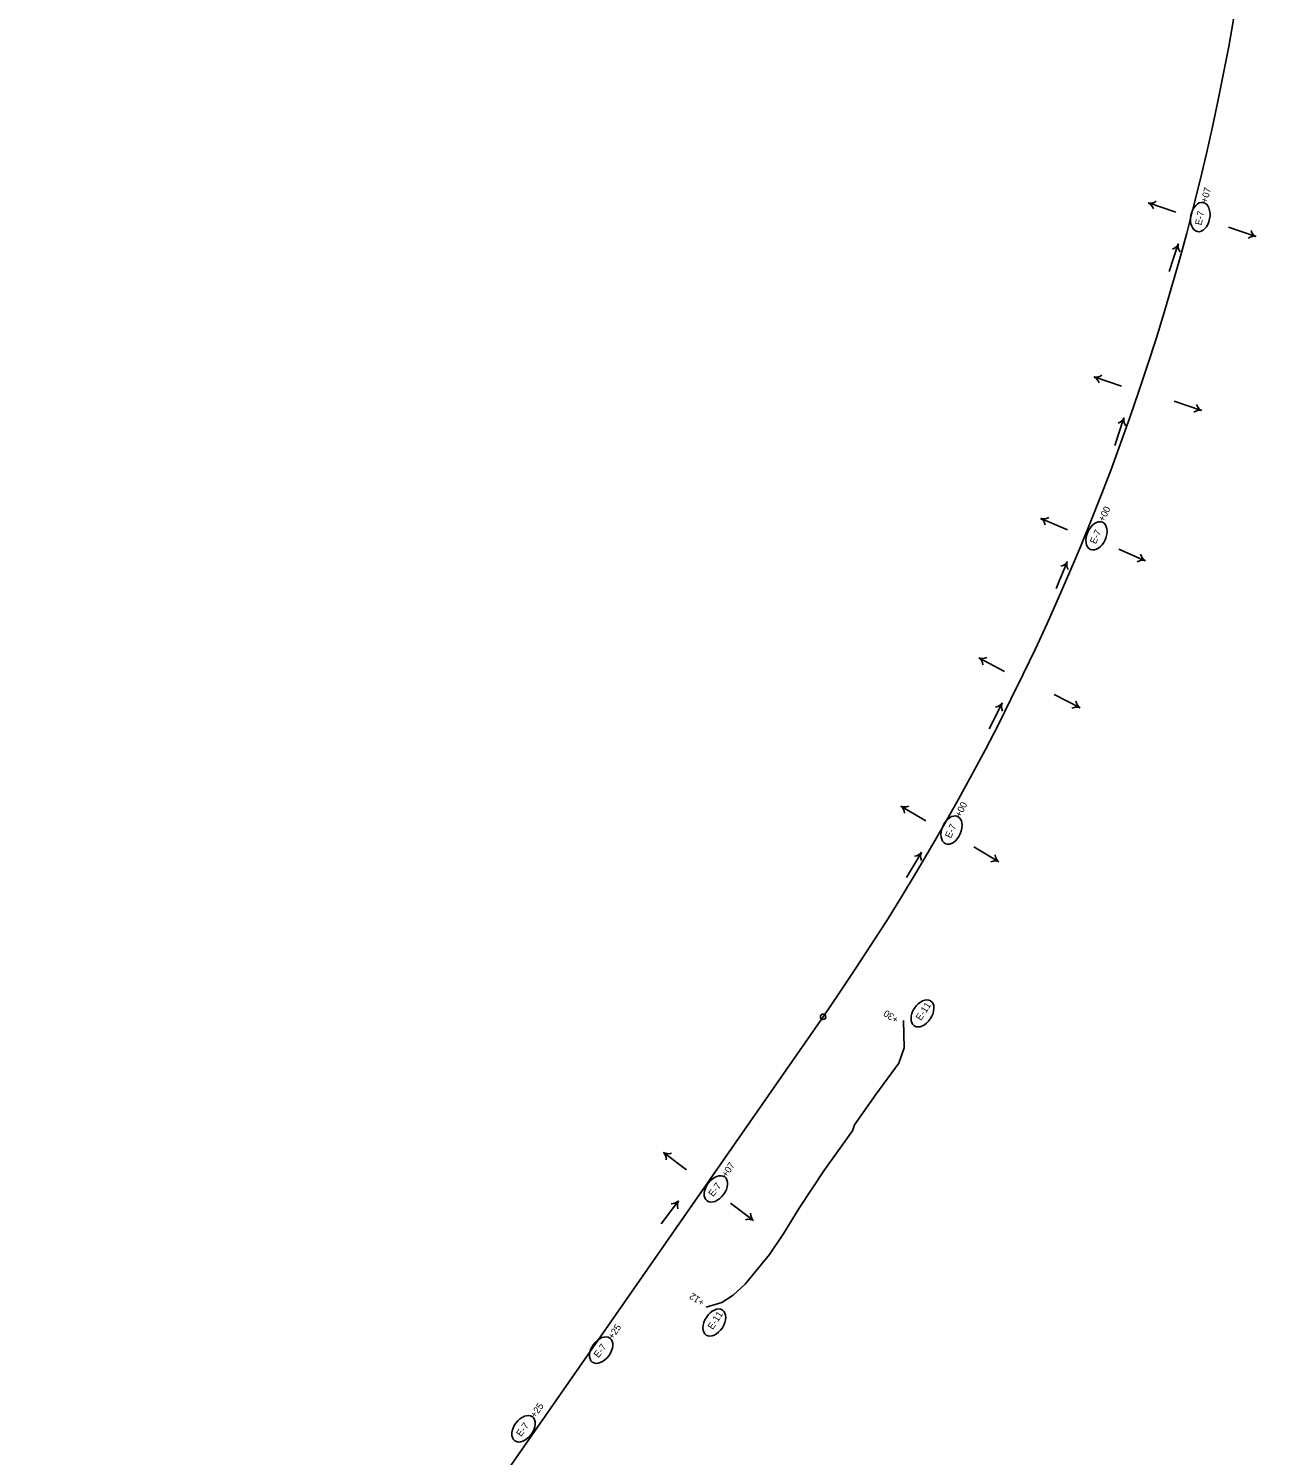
# Model space of a CAD drawing. Extents: x 669236 to 673912, y 735758 to 754788.
# Drawn here: x 672712 to 673851, y 748174 to 749484 of the extents above; entities that cross this region are included whole.
import ezdxf

# ---------------------------------------------------------------- set-up
doc = ezdxf.new("R2010")
doc.units = 0
for name, color, linetype in [('Default', 7, 'Continuous'), ('Prop_Horiz Alignment', 7, 'Continuous'), ('R_Erosion_2', 7, 'Continuous'), ('R_Flow Arrows', 7, 'Continuous')]:
    doc.layers.add(name, color=color, linetype=linetype)

msp = doc.modelspace()

# ---------------------------------------------------------------- linework, layer by layer
at = {"layer": 'Default'}
msp.add_line((671572, 745891.2), (673440.9, 748577.2), dxfattribs=at)
msp.add_arc((671559.6, 749886.2), 2291.8, 325.1701, 46.1906, dxfattribs=at)
at = {"layer": 'Prop_Horiz Alignment'}
msp.add_circle((673440.9, 748577.2), 2.5, dxfattribs=at)
at = {"layer": 'R_Erosion_2'}
msp.add_lwpolyline([(673333.6, 748310.7), (673348.1, 748314.8), (673358.3, 748321.7), (673369.3, 748331.7), (673391.6, 748358.9), (673404.8, 748378.7), (673418.8, 748401.5), (673441.5, 748435.8), (673467.8, 748472.5), (673469.6, 748478.1), (673489.4, 748506), (673510.4, 748534.7), (673515.2, 748548.7), (673514.6, 748573.8)], dxfattribs=at)
for centre, major_axis in [((673787.1, 749311.4), (2.6, 13.4)), ((673691.8, 749018.7), (5.5, 12.5)), ((673558.8, 748748.6), (5.5, 12.5)), ((673532.1, 748580.3), (7.5, 11.5)), ((673342.5, 748419.2), (8.1, 11)), ((673341.1, 748296.5), (7.5, 11.5)), ((673237.2, 748271.2), (8.1, 11)), ((673166, 748199), (8.1, 11))]:
    msp.add_ellipse(centre, major_axis=major_axis, ratio=0.638788, dxfattribs=at)
at = {"layer": 'R_Flow Arrows'}
for p, q in [((673739.5, 749324.3), (673764.7, 749315.8)), ((673838.2, 749293.5), (673813, 749302)), ((673766.9, 749286.7), (673758.6, 749261.5)), ((673689.6, 749164.6), (673714.8, 749156.1)), ((673788.3, 749133.7), (673763.1, 749142.2)), ((673717, 749127), (673708.7, 749101.7)), ((673640.7, 749034.7), (673665.1, 749024.2)), ((673736.6, 748995.9), (673712.2, 749006.4)), ((673665, 748994.9), (673654.7, 748970.5)), ((673583.9, 748906.6), (673607.5, 748894.3)), ((673676.7, 748860.9), (673653.1, 748873.2)), ((673605.2, 748865.2), (673593.2, 748841.5)), ((673512.3, 748770.6), (673535.1, 748757)), ((673602.2, 748719.5), (673579.4, 748733.1)), ((673531.1, 748728.1), (673517.6, 748705.2)), ((673294.4, 748452.7), (673315.5, 748436.6)), ((673308.3, 748408.3), (673292.4, 748387)), ((673377, 748390.1), (673355.8, 748406.2))]:
    msp.add_line(p, q, dxfattribs=at)
for centre, major_axis, start_param, end_param in [((673732.6, 749305.4), (6.4, 19.1), 5.662936, 6.259934), ((673745.7, 749343.5), (-6.4, -19.1), 0.023252, 0.620249), ((673832, 749274.3), (6.4, 19.1), 0.023252, 0.620249), ((673845.1, 749312.4), (-6.4, -19.1), 5.662936, 6.259934), ((673747.9, 749293.4), (19.2, -6.3), 5.662936, 6.259934), ((673786.2, 749280.7), (-19.2, 6.3), 0.023252, 0.620249), ((673682.7, 749145.6), (6.4, 19.1), 5.662936, 6.259934), ((673695.8, 749183.8), (-6.4, -19.1), 0.023252, 0.620249), ((673795.2, 749152.7), (-6.4, -19.1), 5.662936, 6.259934), ((673698, 749133.7), (19.2, -6.3), 5.662936, 6.259934), ((673736.3, 749121), (-19.2, 6.3), 0.023252, 0.620249), ((673782.1, 749114.6), (6.4, 19.1), 0.023252, 0.620249), ((673632.3, 749016.3), (8, 18.5), 5.662936, 6.259934), ((673648.4, 749053.3), (-8, -18.5), 0.023252, 0.620249), ((673646.6, 749003.2), (18.6, -7.8), 5.662936, 6.259934), ((673683.6, 748987.4), (-18.6, 7.8), 0.023252, 0.620249), ((673728.8, 748977.3), (8, 18.5), 0.023252, 0.620249), ((673744.9, 749014.2), (-8, -18.5), 5.662936, 6.259934), ((673574.2, 748888.9), (9.3, 17.9), 5.662936, 6.259934), ((673593, 748924.6), (-9.3, -17.9), 0.023252, 0.620249), ((673587.5, 748874.7), (18, -9.1), 5.662936, 6.259934), ((673623.3, 748856.3), (-18, 9.1), 0.023252, 0.620249), ((673667.6, 748842.9), (9.3, 17.9), 0.023252, 0.620249), ((673686.4, 748878.6), (-9.3, -17.9), 5.662936, 6.259934), ((673501.6, 748753.6), (10.4, 17.3), 5.662936, 6.259934), ((673522.4, 748788.1), (-10.4, -17.3), 0.023252, 0.620249), ((673513.9, 748738.6), (17.4, -10.2), 5.662936, 6.259934), ((673548.6, 748718.1), (-17.4, 10.2), 0.023252, 0.620249), ((673592, 748702), (10.4, 17.3), 0.023252, 0.620249), ((673612.9, 748736.5), (-10.4, -17.3), 5.662936, 6.259934), ((673281.8, 748436.9), (12.2, 16), 5.662936, 6.259934), ((673306.4, 748468.9), (-12.2, -16), 0.023252, 0.620249), ((673292.4, 748420.7), (16.1, -12.1), 5.662936, 6.259934), ((673324.6, 748396.4), (-16.1, 12.1), 0.023252, 0.620249), ((673365, 748373.9), (12.2, 16), 0.023252, 0.620249), ((673389.5, 748405.9), (-12.2, -16), 5.662936, 6.259934)]:
    msp.add_ellipse(centre, major_axis=major_axis, ratio=0.5625, start_param=start_param, end_param=end_param, dxfattribs=at)

# ---------------------------------------------------------------- texts
at = {"layer": 'R_Erosion_2'}
for s, rotation, p in [('+07', 74.6242, (673793.3, 749323.9)), ('E-7', 78.8894, (673788.3, 749303.5)), ('+00', 63.4208, (673698.6, 749031.1)), ('E-7', 66.359, (673691.2, 749010.7)), ('+00', 63.4208, (673567.1, 748759.8)), ('E-7', 66.359, (673558.2, 748740.6)), ('E-11', 56.9613, (673530.7, 748573.2)), ('+30', 146.1843, (673510.8, 748576)), ('+07', 55.5768, (673352.3, 748429.2)), ('E-7', 53.5441, (673340.1, 748411.5)), ('+12', 146.1843, (673332.7, 748316.4)), ('E-11', 56.9613, (673339.7, 748289.5)), ('+25', 55.5768, (673248, 748280.6)), ('E-7', 53.5441, (673234.8, 748263.6)), ('+25', 55.5768, (673176.8, 748208.4)), ('E-7', 53.5441, (673163.7, 748191.3))]:
    msp.add_text(s, height=6.25, rotation=rotation, dxfattribs=at).set_placement(p)

doc.saveas('drawing.dxf')
